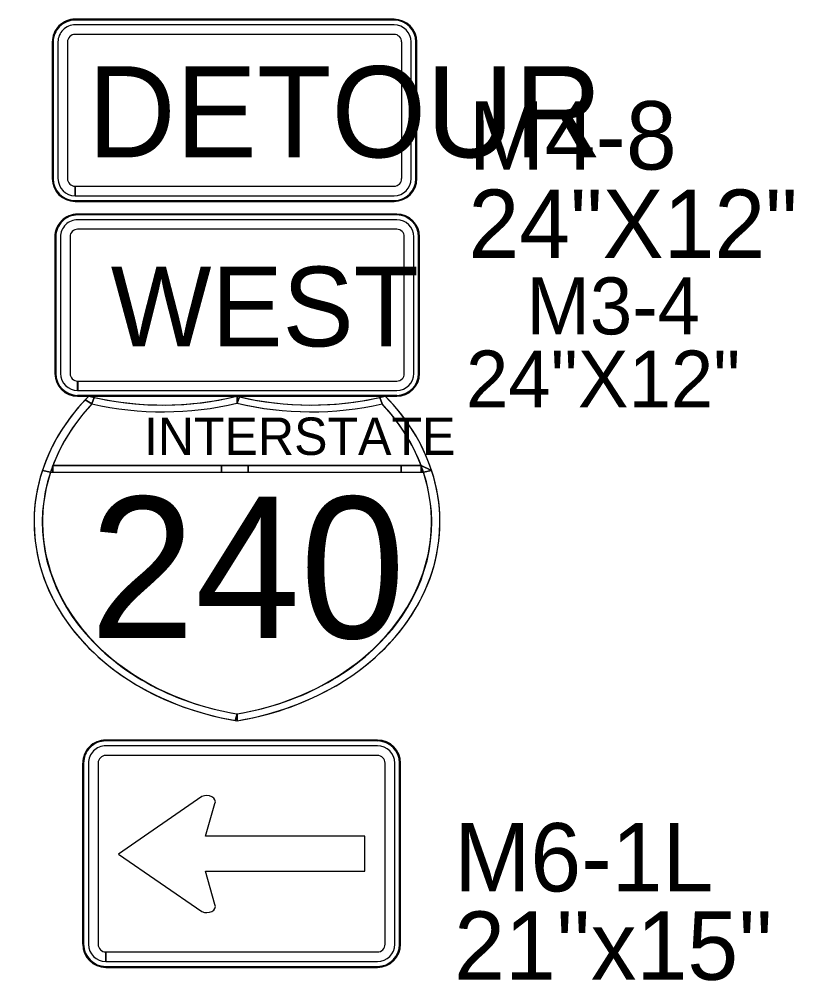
# Model space of a CAD drawing. Extents: x 886234 to 968767, y 455416 to 684046.
# Drawn here: x 910522 to 911542, y 516970 to 518236 of the extents above; entities that cross this region are included whole.
import ezdxf

# ---------------------------------------------------------------- set-up
doc = ezdxf.new("R2010")
doc.units = 0
for name, color, linetype in [('TC DEV SIGN BLACK 239', 7, 'Continuous'), ('TC DEV SIGN BLACK ZERO', 7, 'Continuous'), ('TC DEV SIGN ORANGE', 7, 'Continuous'), ('TC DEV SIGN WHITE', 7, 'Continuous'), ('TC LABEL TEXT', 7, 'Continuous')]:
    doc.layers.add(name, color=color, linetype=linetype)

msp = doc.modelspace()

# ---------------------------------------------------------------- linework, layer by layer
at = {"layer": 'TC DEV SIGN BLACK 239'}
for p, q in [((911019.4, 517972.1), (910599.3, 517972.1)), ((911019.4, 517959.6), (910599.3, 517959.6)), ((910576.8, 517949.6), (910576.8, 517769.6)), ((910589.3, 517949.6), (910589.3, 517769.6)), ((911029.4, 517769.6), (911029.4, 517949.6)), ((911041.9, 517769.6), (911041.9, 517949.6)), ((910599.3, 517747.1), (910599.3, 517759.6)), ((910599.4, 517759.6), (911019.4, 517759.6)), ((910599.4, 517759.6), (910599.4, 517747.1)), ((910599.4, 517747.1), (911019.4, 517747.1)), ((910994, 517279.2), (910636.3, 517279.2)), ((910613.4, 517256.4), (910613.4, 517017.8)), ((910626.1, 517256.4), (910626.1, 517017.8)), ((910994, 517266.5), (910636.3, 517266.5)), ((911004.2, 517017.8), (911004.2, 517256.4)), ((911016.9, 517017.8), (911016.9, 517256.4)), ((910762.9, 517212.4), (910652.9, 517136.6)), ((910767.7, 517160), (910780.1, 517203.1)), ((910977.6, 517160), (910767.7, 517160)), ((910977.6, 517114), (910977.6, 517160)), ((910652.9, 517136.6), (910762.9, 517060.9)), ((910780.1, 517070.1), (910767.7, 517114)), ((910767.7, 517114), (910977.6, 517114)), ((910636.3, 516995), (910636.3, 517007.7)), ((910636.4, 517007.7), (910994, 517007.7)), ((910636.4, 517007.7), (910636.4, 516995)), ((910636.4, 516995), (910994, 516995))]:
    msp.add_line(p, q, dxfattribs=at)
for centre, major_axis, ratio, start_param, end_param in [((910599.3, 517949.6), (22.5, 0), 0.999865, 1.570796, 3.141593), ((911019.4, 517949.6), (22.5, 0), 0.999865, 0, 1.570796), ((910599.3, 517949.6), (10, 0), 0.999865, 1.570796, 3.141593), ((911019.4, 517949.6), (10, 0), 0.999865, 0, 1.570796), ((910599.3, 517769.6), (22.5, 0), 0.999865, 3.141593, 4.712389), ((910599.3, 517769.6), (10, 0), 0.999865, 3.141593, 4.712389), ((911019.4, 517769.6), (22.5, 0), 0.999865, 4.712389, 6.283185), ((911019.4, 517769.6), (10, 0), 0.999865, 4.712389, 6.283185), ((910636.3, 517256.4), (22.8, 0), 0.999865, 1.570796, 3.141593), ((910994, 517256.4), (22.8, 0), 0.999865, 0, 1.570796), ((910636.3, 517256.4), (10.1, 0), 0.999865, 1.570796, 3.141593), ((910994, 517256.4), (10.1, 0), 0.999865, 0, 1.570796), ((910769.3, 517205.6), (-11.3, 0), 0.720018, 2.830616, 5.313575), ((910769.3, 517067.6), (-11.3, 0), 0.720018, 0.969609, 3.452568), ((910636.3, 517017.8), (22.8, 0), 0.999865, 3.141593, 4.712389), ((910636.3, 517017.8), (10.1, 0), 0.999865, 3.141593, 4.712389), ((910994, 517017.8), (22.8, 0), 0.999865, 4.712389, 6.283185), ((910994, 517017.8), (10.1, 0), 0.999865, 4.712389, 6.283185)]:
    msp.add_ellipse(centre, major_axis=major_axis, ratio=ratio, start_param=start_param, end_param=end_param, dxfattribs=at)
at = {"layer": 'TC DEV SIGN BLACK ZERO'}
for p, q in [((911015.9, 518236.2), (910595.9, 518236.2)), ((910595.9, 518234.9), (910595.9, 518234.9)), ((911015.9, 518234.9), (910595.9, 518234.9)), ((911015.9, 518234.9), (911015.9, 518234.9)), ((911015.9, 518228.7), (910595.9, 518228.7)), ((910565.9, 518206.2), (910565.9, 518026.2)), ((910567.1, 518206.2), (910567.1, 518026.2)), ((910567.1, 518206.2), (910567.1, 518206.2)), ((910573.4, 518206.2), (910573.4, 518026.2)), ((910585.9, 518206.2), (910585.9, 518026.2)), ((911015.9, 518216.2), (910595.9, 518216.2)), ((911026, 518026.2), (911026, 518206.2)), ((911038.5, 518026.2), (911038.5, 518206.2)), ((911044.7, 518206.2), (911044.7, 518206.2)), ((911044.7, 518026.2), (911044.7, 518206.2)), ((911046, 518026.2), (911046, 518206.2)), ((910567.1, 518026.2), (910567.1, 518026.2)), ((910595.9, 518003.7), (910595.9, 518016.2)), ((910596, 518016.2), (911015.9, 518016.2)), ((910596, 518016.2), (910596, 518003.7)), ((911044.7, 518026.2), (911044.7, 518026.2)), ((910596, 518003.7), (911015.9, 518003.7)), ((910595.9, 517996.2), (910595.9, 517997.4)), ((910595.9, 517997.4), (910595.9, 517997.4)), ((910595.9, 517997.4), (911015.9, 517997.4)), ((910595.9, 517997.4), (910595.9, 517996.2)), ((910595.9, 517996.2), (911015.9, 517996.2)), ((911015.9, 517997.4), (911015.9, 517997.4)), ((911019.4, 517979.6), (910599.3, 517979.6)), ((910599.3, 517978.4), (910599.3, 517978.4)), ((911019.4, 517978.4), (910599.3, 517978.4)), ((911019.4, 517978.4), (911019.4, 517978.4)), ((910569.3, 517949.6), (910569.3, 517769.6)), ((910570.5, 517949.6), (910570.5, 517769.6)), ((910570.5, 517949.6), (910570.6, 517949.6)), ((911048.1, 517949.6), (911048.1, 517949.6)), ((911048.1, 517769.6), (911048.1, 517949.6)), ((911049.4, 517769.6), (911049.4, 517949.6)), ((910570.6, 517769.6), (910570.5, 517769.6)), ((911048.1, 517769.6), (911048.1, 517769.6)), ((910599.3, 517739.6), (910599.3, 517740.9)), ((910599.3, 517740.9), (910599.3, 517740.9)), ((910599.3, 517740.9), (911019.4, 517740.9)), ((910599.3, 517740.9), (910599.3, 517739.6)), ((910599.3, 517739.6), (911019.4, 517739.6)), ((910618, 517729.4), (910621.1, 517738)), ((910809.4, 517730.4), (910809.1, 517739.7)), ((910809.3, 517731.1), (910809.1, 517739.7)), ((910997.1, 517738), (911000.1, 517729.4)), ((911019.4, 517740.9), (911019.4, 517740.9)), ((910566.8, 517648.5), (911051.4, 517648.5)), ((910788.7, 517648.5), (910566.8, 517648.5)), ((910823.9, 517648.5), (910788.7, 517648.5)), ((911025.2, 517648.5), (910823.9, 517648.5)), ((911051.4, 517648.5), (911025.2, 517648.5)), ((911065.3, 517641.9), (911051.4, 517648.5)), ((910563.6, 517639.6), (911054.5, 517639.6)), ((910563.6, 517639.6), (910566.8, 517639.6)), ((910566.8, 517639.6), (910788.7, 517639.6)), ((910788.7, 517639.6), (910823.9, 517639.6)), ((910823.9, 517639.6), (911025.2, 517639.6)), ((911025.2, 517639.6), (911051.4, 517639.6)), ((911054.3, 517640.3), (911051.4, 517639.6)), ((911051.4, 517639.6), (911054.5, 517639.6)), ((910541.9, 517575.3), (910541.9, 517572.7)), ((911076.3, 517572.6), (911076.3, 517575.4)), ((910809.1, 517312.2), (910809.1, 517321.3)), ((910994, 517286.8), (910636.3, 517286.8)), ((910636.3, 517285.5), (910636.3, 517285.6)), ((910994, 517285.5), (910636.3, 517285.6)), ((910994, 517285.5), (910994, 517285.5)), ((910605.8, 517256.4), (910605.8, 517017.8)), ((910607.1, 517256.4), (910607.1, 517017.8)), ((910607.1, 517256.4), (910607.1, 517256.4)), ((911023.2, 517256.4), (911023.2, 517256.4)), ((911023.2, 517017.8), (911023.2, 517256.4)), ((911024.5, 517017.8), (911024.5, 517256.4)), ((910607.1, 517017.8), (910607.1, 517017.8)), ((911023.2, 517017.8), (911023.2, 517017.8)), ((910636.3, 516987.4), (910636.3, 516988.7)), ((910636.3, 516988.7), (910636.3, 516988.7)), ((910636.3, 516988.7), (910994, 516988.7)), ((910636.3, 516988.7), (910636.3, 516987.4)), ((910636.3, 516987.4), (910994, 516987.4)), ((910994, 516988.7), (910994, 516988.7))]:
    msp.add_line(p, q, dxfattribs=at)
for points in [[(910613.9, 517739.7), (910613.9, 517739.7), (910613.9, 517739.7)], [(910621.1, 517738), (910618, 517729.4)], [(910809.3, 517739.6), (910809.3, 517731.1), (910812.5, 517738.9)], [(910812.5, 517738.9), (910809.4, 517730.4)], [(911000.1, 517729.4), (910997.1, 517738)], [(911004.3, 517739.7), (911004.3, 517739.7), (911004.3, 517739.7)], [(910609.2, 517734.8), (910618, 517729.4)], [(910618, 517729.4), (910609.2, 517734.8)], [(910809.1, 517730.4), (910809.3, 517731.1)], [(910566.8, 517648.5), (910566.8, 517639.6)], [(910566.8, 517639.6), (910566.8, 517648.5)], [(910788.7, 517639.6), (910788.7, 517648.5)], [(910788.7, 517648.5), (910788.7, 517639.6)], [(910823.9, 517648.5), (910823.9, 517639.6)], [(910823.9, 517639.6), (910823.9, 517648.5)], [(911025.2, 517639.6), (911025.2, 517648.5)], [(911025.2, 517648.5), (911025.2, 517639.6)], [(911051.4, 517648.5), (911065.3, 517641.9)], [(911051.4, 517639.6), (911051.4, 517648.5)], [(911051.4, 517648.5), (911051.4, 517639.6), (911054.3, 517640.3), (911051.4, 517648.5)], [(910552.9, 517641.9), (910563.6, 517639.6)], [(910563.6, 517639.6), (910552.9, 517641.9)], [(911054.5, 517639.6), (911054.3, 517640.3)], [(911065.3, 517641.9), (911054.5, 517639.6)], [(911054.5, 517639.6), (911065.3, 517641.9)], [(910806.8, 517312.6), (910809.1, 517321.3)], [(910809.1, 517321.3), (910806.8, 517312.6), (910809.1, 517312.2)], [(910809.1, 517321.3), (910809.1, 517312.2)]]:
    msp.add_lwpolyline(points, dxfattribs=at)
for centre, major_axis, ratio, start_param, end_param in [((910595.9, 518206.2), (30, 0), 0.999865, 1.570796, 3.141593), ((910595.9, 518206.2), (28.8, 0), 0.999865, 1.570796, 3.141593), ((911015.9, 518206.2), (30, 0), 0.999865, 0, 1.570796), ((911015.9, 518206.2), (28.8, 0), 0.999865, 0, 1.570796), ((910595.9, 518206.2), (22.5, 0), 0.999865, 1.570796, 3.141593), ((911015.9, 518206.2), (22.5, 0), 0.999865, 0, 1.570796), ((910595.9, 518206.2), (10, 0), 0.999865, 1.570796, 3.141593), ((911015.9, 518206.2), (10, 0), 0.999865, 0, 1.570796), ((910595.9, 518026.2), (30, 0), 0.999865, 3.141593, 4.712389), ((910595.9, 518026.2), (28.8, 0), 0.999865, 3.141593, 4.712389), ((910595.9, 518026.2), (22.5, 0), 0.999865, 3.141593, 4.712389), ((910595.9, 518026.2), (10, 0), 0.999865, 3.141593, 4.712389), ((911015.9, 518026.2), (22.5, 0), 0.999865, 4.712389, 6.283185), ((911015.9, 518026.2), (10, 0), 0.999865, 4.712389, 6.283185), ((911015.9, 518026.2), (30, 0), 0.999865, 4.712389, 6.283185), ((911015.9, 518026.2), (28.8, 0), 0.999865, 4.712389, 6.283185), ((910599.3, 517949.6), (30, 0), 0.999865, 1.570796, 3.141593), ((910599.3, 517949.6), (28.8, 0), 0.999865, 1.570796, 3.141593), ((911019.4, 517949.6), (30, 0), 0.999865, 0, 1.570796), ((911019.4, 517949.6), (28.8, 0), 0.999865, 0, 1.570796), ((910599.3, 517769.6), (30, 0), 0.999865, 3.141593, 4.712389), ((910599.3, 517769.6), (28.8, 0), 0.999865, 3.141593, 4.712389), ((911019.4, 517769.6), (30, 0), 0.999865, 4.712389, 6.283185), ((911019.4, 517769.6), (28.8, 0), 0.999865, 4.712389, 6.283185), ((910875.9, 517574), (-334, 0), 0.800002, 5.614188, 7.652625), ((910875.9, 517574), (-334, 0), 0.800002, 5.614216, 5.637358), ((910711.5, 517995.2), (334, 0), 0.800002, 4.415792, 5.008922), ((910711.5, 517995.2), (334, 0), 0.800002, 4.415856, 4.438209), ((910711.5, 517995.2), (334, 0), 0.800002, 4.438209, 5.008909), ((910906.7, 517995.2), (334, 0), 0.800002, 4.415856, 5.008986), ((910742.3, 517574), (334, 0), 0.800002, 4.913746, 6.952183), ((910906.7, 517995.2), (334, 0), 0.800002, 4.416709, 4.426515), ((910906.7, 517995.2), (334, 0), 0.800002, 4.426515, 4.986569), ((910906.7, 517995.2), (334, 0), 0.800002, 4.986569, 5.008922), ((910742.3, 517574), (334, 0), 0.800002, 0.256966, 0.66897), ((910875.9, 517574), (-322.9, 0), 0.800002, 5.637358, 7.64558), ((910875.9, 517574), (-334, 0), 0.800002, 5.637358, 6.026219), ((910875.9, 517574), (-322.9, 0), 0.800002, 5.637358, 6.026219), ((910711.5, 517995.2), (345.1, 0), 0.800002, 4.438209, 4.999074), ((910711.5, 517995.2), (345.1, 0), 0.800002, 4.438209, 4.999074), ((910906.7, 517995.2), (345.1, 0), 0.800002, 4.425704, 4.986569), ((910742.3, 517574), (322.9, 0), 0.800002, 4.920791, 6.929013), ((910906.8, 517994.8), (344.6, 0), 0.800002, 4.425686, 4.986568), ((910742.3, 517574), (322.9, 0), 0.800002, 0.292795, 0.645828), ((910875.9, 517574), (-322.9, 0), 0.800002, 5.99039, 6.026219), ((910742.3, 517574), (322.9, 0), 0.800002, 0.256966, 0.292795), ((910874.3, 517573.2), (-321.6, 0), 0.800002, 6.022151, 7.649781), ((910875.9, 517574), (-334, 0), 0.800002, 6.026219, 6.278259), ((910743.9, 517573.2), (321.6, 0), 0.800002, 4.916934, 6.544356), ((910742.3, 517574), (334, 0), 0.800002, 0.005231, 0.256966), ((910875.9, 517574), (-334, 0), 0.800002, 0.004927, 1.362388), ((910742.3, 517574), (334, 0), 0.800002, 4.913748, 6.277955), ((910742.3, 517574), (322.9, 0), 0.800002, 4.920791, 4.921138), ((910875.9, 517574), (-334, 0), 0.800002, 1.36935, 1.369438), ((910742.3, 517574), (334, 0), 0.800002, 4.913747, 4.913748), ((910636.3, 517256.4), (30.4, 0), 0.999865, 1.570796, 3.141593), ((910636.3, 517256.4), (29.2, 0), 0.999865, 1.570796, 3.141593), ((910994, 517256.4), (30.4, 0), 0.999865, 0, 1.570796), ((910994, 517256.4), (29.2, 0), 0.999865, 0, 1.570796), ((910636.3, 517017.8), (30.4, 0), 0.999865, 3.141593, 4.712389), ((910636.3, 517017.8), (29.2, 0), 0.999865, 3.141593, 4.712389), ((910994, 517017.8), (30.4, 0), 0.999865, 4.712389, 6.283185), ((910994, 517017.8), (29.2, 0), 0.999865, 4.712389, 6.283185)]:
    msp.add_ellipse(centre, major_axis=major_axis, ratio=ratio, start_param=start_param, end_param=end_param, dxfattribs=at)
at = {"layer": 'TC DEV SIGN ORANGE'}
for p, q in [((911015.9, 518236.2), (910595.9, 518236.2)), ((910565.9, 518206.2), (910565.9, 518026.2)), ((911046, 518026.2), (911046, 518206.2)), ((910595.9, 517996.2), (911015.9, 517996.2))]:
    msp.add_line(p, q, dxfattribs=at)
for centre, start_param, end_param in [((910595.9, 518206.2), 1.570796, 3.141593), ((911015.9, 518206.2), 0, 1.570796), ((910595.9, 518026.2), 3.141593, 4.712389), ((911015.9, 518026.2), 4.712389, 6.283185)]:
    msp.add_ellipse(centre, major_axis=(30, 0), ratio=0.999865, start_param=start_param, end_param=end_param, dxfattribs=at)
at = {"layer": 'TC DEV SIGN WHITE'}
for p, q in [((911019.4, 517979.6), (910599.3, 517979.6)), ((910569.3, 517949.6), (910569.3, 517769.6)), ((911049.4, 517769.6), (911049.4, 517949.6)), ((910599.3, 517739.6), (911019.4, 517739.6)), ((910994, 517286.8), (910636.3, 517286.8)), ((910605.8, 517256.4), (910605.8, 517017.8)), ((911024.5, 517017.8), (911024.5, 517256.4)), ((910636.3, 516987.4), (910994, 516987.4))]:
    msp.add_line(p, q, dxfattribs=at)
for centre, major_axis, start_param, end_param in [((910599.3, 517949.6), (30, 0), 1.570796, 3.141593), ((911019.4, 517949.6), (30, 0), 0, 1.570796), ((910599.3, 517769.6), (30, 0), 3.141593, 4.712389), ((911019.4, 517769.6), (30, 0), 4.712389, 6.283185), ((910636.3, 517256.4), (30.4, 0), 1.570796, 3.141593), ((910994, 517256.4), (30.4, 0), 0, 1.570796), ((910636.3, 517017.8), (30.4, 0), 3.141593, 4.712389), ((910994, 517017.8), (30.4, 0), 4.712389, 6.283185)]:
    msp.add_ellipse(centre, major_axis=major_axis, ratio=0.999865, start_param=start_param, end_param=end_param, dxfattribs=at)

# ---------------------------------------------------------------- texts
at = {"layer": 'TC DEV SIGN BLACK 239'}
msp.add_text('WEST', height=105, rotation=360, dxfattribs=at).set_placement((910642.9, 517805.3))
at = {"layer": 'TC DEV SIGN BLACK ZERO'}
for s, height, p in [('DETOUR', 120, (910612.5, 518054.3)), ('M4-8', 90, (911113.9, 518038.2)), ('24"X12"', 90, (911113.9, 517921.8)), ('INTERSTATE', 49.28, (910686.6, 517662.3)), ('240', 186.16, (910615.3, 517421)), ('M6-1L', 90, (911095.1, 517087.4)), ("21''x15''", 90, (911095.1, 516971))]:
    msp.add_text(s, height=height, rotation=360, dxfattribs=at).set_placement(p)
at = {"layer": 'TC LABEL TEXT'}
for s, p in [('M3-4', (911190.2, 517821.1)), ('24"X12"', (911110.6, 517724.8))]:
    msp.add_text(s, height=75, dxfattribs=at).set_placement(p)

doc.saveas('drawing.dxf')
